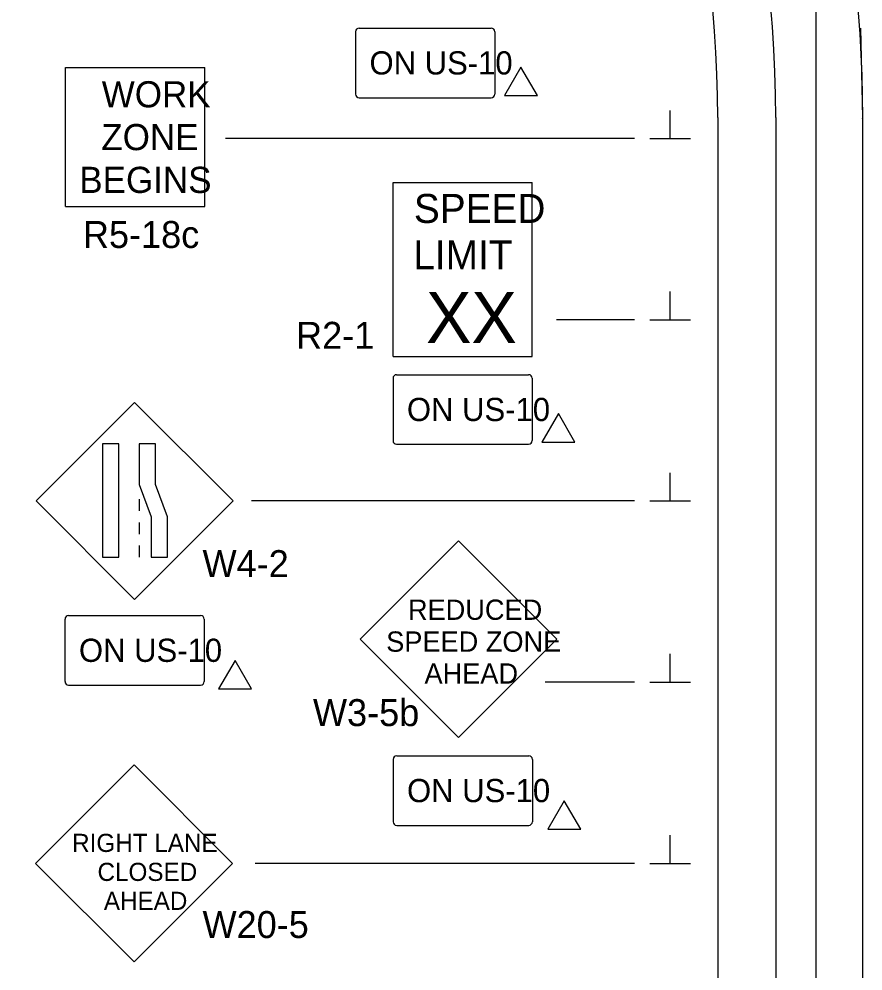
# Model space of a CAD drawing. Extents: x 16751 to 18479, y 5718 to 6974.
# Drawn here: x 16761 to 16993.7, y 6289.6 to 6552.3 of the extents above; entities that cross this region are included whole.
import ezdxf

# ---------------------------------------------------------------- set-up
doc = ezdxf.new("R2010")
doc.units = 0
for name, color, linetype in [('ALI_LEGAL_EX', 7, 'Continuous'), ('PAVT_EDGE_EX', 7, 'Continuous'), ('TRAFFIC_SIGNS_PR', 7, 'Continuous'), ('TYPICAL_TEXT_DIMEN_PR', 7, 'Continuous')]:
    doc.layers.add(name, color=color, linetype=linetype)

msp = doc.modelspace()

# ---------------------------------------------------------------- linework, layer by layer
at = {"layer": 'ALI_LEGAL_EX'}
for p, q in [((16980.68, 6974.12), (16980.68, 6155.98)), ((16980.68, 6877.04), (16980.68, 6013.12)), ((16993.65, 6024.8), (16993.65, 6525.15))]:
    msp.add_line(p, q, dxfattribs=at)
for points in [[(16993.6, 6524.8), (16993.65, 6525.15), (16993.08, 6549.79)], [(16993.65, 6424.8), (16993.65, 6449.8)], [(16993.7, 6324.8), (16993.7, 6349.8)]]:
    msp.add_lwpolyline(points, dxfattribs=at)
msp.add_arc((16629.65, 6525.15), 364, 0, 57.2958, dxfattribs=at)
at = {"layer": 'PAVT_EDGE_EX'}
for p, q in [((16953.65, 6525.15), (16953.65, 6186.91)), ((16969.65, 6525.15), (16969.65, 6186.91))]:
    msp.add_line(p, q, dxfattribs=at)
for radius in [340, 324]:
    msp.add_arc((16629.65, 6525.15), radius, 0, 66.0906, dxfattribs=at)
at = {"layer": 'TRAFFIC_SIGNS_PR'}
for p, q in [((16854.78, 6549.83), (16891.18, 6549.83)), ((16853.78, 6548.83), (16853.78, 6531.63)), ((16892.18, 6548.83), (16892.18, 6531.63)), ((16773.77, 6500.59), (16773.77, 6538.99)), ((16773.77, 6538.99), (16812.17, 6538.99)), ((16812.17, 6500.59), (16812.17, 6538.99)), ((16854.78, 6530.63), (16891.18, 6530.63)), ((16864.1, 6507.19), (16902.5, 6507.19)), ((16864.1, 6459.19), (16864.1, 6507.19)), ((16902.5, 6459.19), (16902.5, 6507.19)), ((16773.77, 6500.59), (16812.17, 6500.59)), ((16864.1, 6459.19), (16902.5, 6459.19)), ((16864.1, 6453.19), (16864.1, 6435.99)), ((16865.1, 6454.19), (16901.5, 6454.19)), ((16902.5, 6453.19), (16902.5, 6435.99)), ((16792.84, 6446.48), (16765.68, 6419.33)), ((16819.99, 6419.33), (16792.84, 6446.48)), ((16865.1, 6434.99), (16901.5, 6434.99)), ((16765.68, 6419.33), (16792.84, 6392.17)), ((16792.84, 6392.17), (16819.99, 6419.33)), ((16794.08, 6419.82), (16794.08, 6416.62)), ((16794.08, 6413.42), (16794.08, 6410.22)), ((16882.17, 6408.37), (16855.01, 6381.22)), ((16909.32, 6381.22), (16882.17, 6408.37)), ((16794.08, 6407.02), (16794.08, 6403.82)), ((16773.63, 6386.73), (16773.63, 6369.53)), ((16774.63, 6387.73), (16811.04, 6387.73)), ((16812.04, 6386.73), (16812.04, 6369.53)), ((16855.01, 6381.22), (16882.17, 6354.07)), ((16882.17, 6354.07), (16909.32, 6381.22)), ((16774.63, 6368.53), (16811.04, 6368.53)), ((16864.12, 6348.02), (16864.12, 6330.82)), ((16865.12, 6349.02), (16901.52, 6349.02)), ((16902.52, 6348.02), (16902.52, 6330.82)), ((16792.67, 6346.48), (16765.52, 6319.33)), ((16819.82, 6319.33), (16792.67, 6346.48)), ((16865.12, 6329.82), (16901.52, 6329.82)), ((16765.52, 6319.33), (16792.67, 6292.18)), ((16792.67, 6292.18), (16819.82, 6319.33))]:
    msp.add_line(p, q, dxfattribs=at)
for points in [[(16783.94, 6435.06), (16783.94, 6403.82), (16788.44, 6403.82), (16788.44, 6435.06)], [(16794.08, 6435.06), (16794.08, 6423.88), (16797.42, 6415), (16797.42, 6403.82), (16801.92, 6403.82), (16801.92, 6415), (16798.57, 6423.88), (16798.57, 6435.06)]]:
    msp.add_lwpolyline(points, close=True, dxfattribs=at)
for centre, start, end in [((16854.78, 6548.83), 90, 180), ((16891.18, 6548.83), 0, 90), ((16854.78, 6531.63), 180, 270), ((16891.18, 6531.63), 270, 0), ((16865.1, 6453.19), 90, 180), ((16901.5, 6453.19), 0, 90), ((16865.1, 6435.99), 180, 270), ((16901.5, 6435.99), 270, 0), ((16774.64, 6386.73), 90, 180), ((16811.04, 6386.73), 0, 90), ((16774.64, 6369.53), 180, 270), ((16811.04, 6369.53), 270, 0), ((16865.12, 6348.02), 90, 180), ((16901.52, 6348.02), 0, 90), ((16865.12, 6330.82), 180, 270), ((16901.52, 6330.82), 270, 0)]:
    msp.add_arc(centre, 1, start, end, dxfattribs=at)
at = {"layer": 'TYPICAL_TEXT_DIMEN_PR'}
for p, q in [((16940.52, 6519.33), (16940.52, 6527.11)), ((16930.65, 6519.33), (16817.88, 6519.33)), ((16934.9, 6519.33), (16946.15, 6519.33)), ((16940.52, 6469.33), (16940.52, 6477.11)), ((16930.65, 6469.33), (16909.21, 6469.33)), ((16934.9, 6469.33), (16946.15, 6469.33)), ((16940.52, 6419.33), (16940.52, 6427.11)), ((16930.65, 6419.33), (16825.08, 6419.33)), ((16934.9, 6419.33), (16946.15, 6419.33)), ((16940.52, 6369.33), (16940.52, 6377.11)), ((16930.65, 6369.33), (16906.03, 6369.33)), ((16934.9, 6369.33), (16946.15, 6369.33)), ((16940.52, 6319.33), (16940.52, 6327.11)), ((16930.65, 6319.33), (16826.11, 6319.33)), ((16934.9, 6319.33), (16946.15, 6319.33))]:
    msp.add_line(p, q, dxfattribs=at)
for points in [[(16899.38, 6539.08), (16894.85, 6531.24), (16903.9, 6531.24)], [(16909.7, 6443.44), (16905.17, 6435.61), (16914.22, 6435.61)], [(16820.53, 6375.32), (16816.01, 6367.48), (16825.06, 6367.48)], [(16911.34, 6336.6), (16906.81, 6328.77), (16915.86, 6328.77)]]:
    msp.add_lwpolyline(points, close=True, dxfattribs=at)

# ---------------------------------------------------------------- texts
at = {"layer": 'TRAFFIC_SIGNS_PR'}
for s, height, p in [('ON US-10', 6.4, (16857.61, 6537.03)), ('WORK', 7.217, (16783.77, 6527.96)), ('ZONE', 7.217, (16783.65, 6516.15)), ('BEGINS', 7.217, (16777.58, 6504.34)), ('SPEED', 8, (16869.86, 6496.06)), ('R5-18c', 7.44, (16778.58, 6489.15)), ('LIMIT', 8, (16869.7, 6483.26)), ('XX', 14.031, (16873.21, 6462.95)), ('R2-1', 7.44, (16837.37, 6461.33)), ('ON US-10', 6.4, (16867.93, 6441.39)), ('W4-2', 7.441, (16811.57, 6398.32)), ('REDUCED', 5.6, (16868.22, 6386.53)), ('ON US-10', 6.401, (16777.48, 6374.93)), ('SPEED ZONE', 5.6, (16862.22, 6377.73)), ('AHEAD', 5.6, (16872.78, 6368.93)), ('W3-5b', 7.44, (16842.03, 6357.21)), ('ON US-10', 6.4, (16867.96, 6336.22)), ('RIGHT LANE', 4.999, (16775.61, 6322.48)), ('CLOSED', 4.999, (16782.6, 6314.48)), ('AHEAD', 4.999, (16784.35, 6306.49)), ('W20-5', 7.439, (16811.57, 6298.73))]:
    msp.add_text(s, height=height, dxfattribs=at).set_placement(p)

doc.saveas('drawing.dxf')
